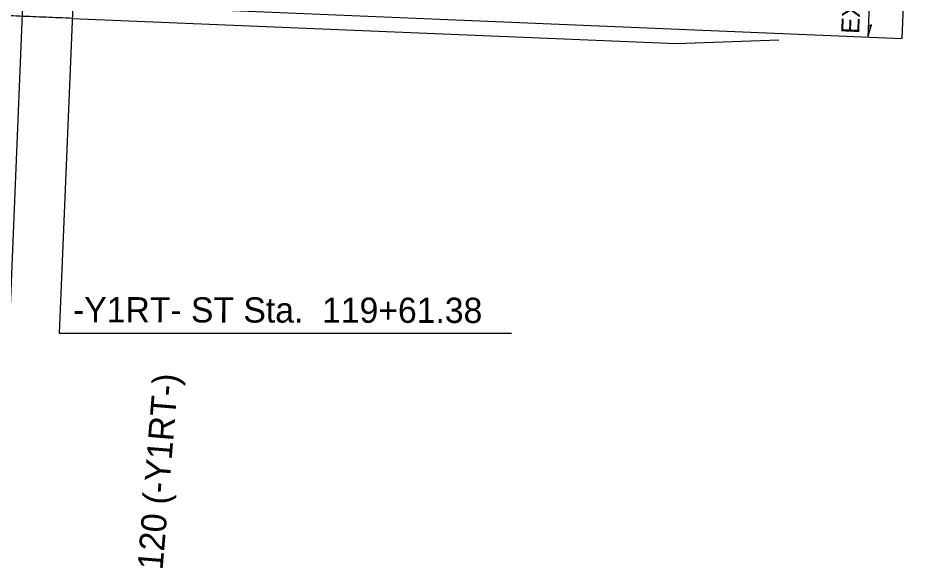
# Model space of a CAD drawing. Extents: x 2389694 to 2405615, y 546931 to 573532.
# Drawn here: x 2399801.2 to 2400051.5, y 552200.2 to 552352.9 of the extents above; entities that cross this region are included whole.
import ezdxf

# ---------------------------------------------------------------- set-up
doc = ezdxf.new("R2010")
doc.units = 0
for name, color, linetype in [('Prop EOT', 7, 'Continuous'), ('Prop Horizontal Alignment Curve and Spiral Data', 7, 'Continuous'), ('Prop Super Arrow 1 Lane CELL', 7, 'Continuous'), ('Prop Superelevation Label', 7, 'Continuous')]:
    doc.layers.add(name, color=color, linetype=linetype)

msp = doc.modelspace()

# ---------------------------------------------------------------- linework, layer by layer
at = {"layer": 'Prop EOT'}
for p, q in [((2400046.82, 552347.3), (2400051.46, 552459.22)), ((2399816.48, 552356.84), (2400046.82, 552347.3)), ((2399816.32, 552352.84), (2399984.12, 552345.89)), ((2399984.12, 552345.89), (2400012.51, 552346.92))]:
    msp.add_line(p, q, dxfattribs=at)
msp.add_spline([(2399816.32, 552352.84), (2399812.67, 552352.99), (2399809.02, 552353.14), (2399805.38, 552353.3), (2399801.73, 552353.45), (2399798.08, 552353.6), (2399794.44, 552353.75), (2399790.79, 552353.9), (2399787.14, 552354.06), (2399783.49, 552354.21), (2399779.84, 552354.36), (2399776.19, 552354.52), (2399772.54, 552354.67), (2399768.89, 552354.83), (2399765.24, 552354.98), (2399761.59, 552355.14), (2399757.94, 552355.3), (2399754.28, 552355.46), (2399750.63, 552355.62), (2399746.98, 552355.78), (2399743.33, 552355.94), (2399739.67, 552356.1), (2399736.02, 552356.27), (2399732.36, 552356.43), (2399728.71, 552356.6), (2399725.05, 552356.76), (2399721.4, 552356.93), (2399717.74, 552357.1), (2399714.09, 552357.28), (2399710.43, 552357.45), (2399706.77, 552357.62), (2399703.12, 552357.8), (2399699.46, 552357.98), (2399695.8, 552358.16), (2399692.14, 552358.34), (2399688.49, 552358.53), (2399684.83, 552358.71), (2399681.17, 552358.9), (2399677.51, 552359.09), (2399673.85, 552359.28), (2399670.19, 552359.48), (2399666.53, 552359.67), (2399662.87, 552359.87), (2399659.21, 552360.07), (2399655.55, 552360.28), (2399651.89, 552360.48), (2399648.22, 552360.69), (2399644.56, 552360.9), (2399640.9, 552361.11), (2399637.24, 552361.33), (2399633.57, 552361.55), (2399629.91, 552361.77), (2399626.25, 552361.99), (2399622.58, 552362.22), (2399618.92, 552362.45), (2399615.26, 552362.68), (2399611.59, 552362.92), (2399607.93, 552363.16), (2399604.26, 552363.4), (2399600.6, 552363.64), (2399596.93, 552363.89), (2399593.27, 552364.14), (2399589.6, 552364.4), (2399585.94, 552364.66), (2399582.27, 552364.92), (2399578.61, 552365.18), (2399574.94, 552365.45), (2399571.27, 552365.73), (2399567.61, 552366), (2399563.94, 552366.28), (2399560.27, 552366.57), (2399556.61, 552366.85), (2399552.94, 552367.14), (2399549.27, 552367.44), (2399545.62, 552367.74)], degree=3, dxfattribs=at)
at = {"layer": 'Prop Horizontal Alignment Curve and Spiral Data'}
for p, q in [((2399804.76, 552410.87), (2399796.98, 552223.11)), ((2399817.41, 552379.32), (2399812.69, 552265.4)), ((2399812.69, 552265.4), (2399938.28, 552265.4))]:
    msp.add_line(p, q, dxfattribs=at)
at = {"layer": 'Prop Super Arrow 1 Lane CELL'}
msp.add_line((2400038.28, 552371.67), (2400037.28, 552347.61), dxfattribs=at)
msp.add_lwpolyline([(2400037.28, 552347.61), (2400038.23, 552351.07), (2400037.41, 552350.56)], close=True, dxfattribs=at)

# ---------------------------------------------------------------- texts
at = {"layer": 'Prop Horizontal Alignment Curve and Spiral Data'}
for s, rotation, p in [('-Y1RT- ST Sta.  119+61.38', 359.8937, (2399816.49, 552268.46)), ('120 (-Y1RT-)', 85.2956, (2399841.36, 552199.5))]:
    msp.add_text(s, height=7, rotation=rotation, dxfattribs=at).set_placement(p)
at = {"layer": 'Prop Superelevation Label'}
msp.add_text('EXIST.', height=5, rotation=87.6277, dxfattribs=at).set_placement((2400034.83, 552348.5))

doc.saveas('drawing.dxf')
